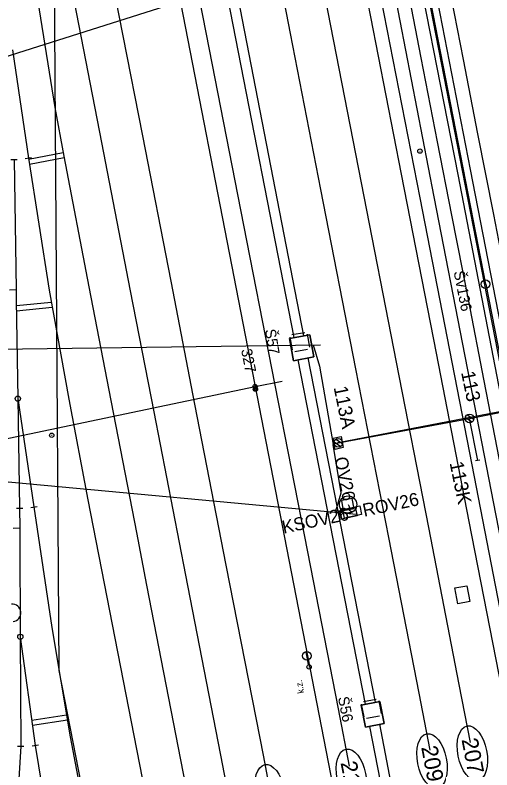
# Model space of a CAD drawing. Extents: x -545846 to -545044, y -1122650 to -1119108.
# Drawn here: x -545610 to -545555, y -1120099.3 to -1120012.2 of the extents above; entities that cross this region are included whole.
import ezdxf

# ---------------------------------------------------------------- set-up
doc = ezdxf.new("R2010")
doc.units = 0
for name, color, linetype in [('osvětlené plochy-hodnota-obrys', 7, 'Continuous'), ('Vrstva 1', 7, 'Continuous'), ('Vrstva 1 - Koleje', 7, 'Continuous'), ('Vrstva 11', 7, 'Continuous'), ('Vrstva 11 - Trakce', 7, 'Continuous'), ('Vrstva 12', 7, 'Continuous'), ('Vrstva 12 - Trakce zaklady', 7, 'Continuous'), ('Vrstva 2', 7, 'Continuous'), ('Vrstva 25', 7, 'Continuous'), ('Vrstva 26', 7, 'Continuous'), ('Vrstva 28', 7, 'Continuous'), ('Vrstva 34', 7, 'Continuous'), ('Vrstva 35', 7, 'Continuous'), ('Vrstva 36', 7, 'Continuous'), ('Vrstva 4 - Teren - stezky - prechody - plochy', 7, 'Continuous'), ('Vrstva 43', 7, 'Continuous'), ('Vrstva 44', 7, 'Continuous'), ('Vrstva 47', 7, 'Continuous'), ('Vrstva 50', 7, 'Continuous'), ('Vrstva 63', 7, 'Continuous'), ('Vrstva 7', 7, 'Continuous')]:
    doc.layers.add(name, color=color, linetype=linetype)

msp = doc.modelspace()

# ---------------------------------------------------------------- linework, layer by layer
at = {"layer": 'osvětlené plochy-hodnota-obrys'}
for points in [[(-545611.105, -1119760.367), (-545492.389, -1120368.615), (-545475.582, -1120447.487)], [(-545604.967, -1120087.817), (-545606.006, -1119933.661)], [(-545605.8, -1119934.355), (-545489.142, -1120534.587)], [(-545615.945, -1120078.719), (-545593.529, -1120193.57), (-545569.431, -1120317.038), (-545566.209, -1120328.419), (-545557.447, -1120326.084), (-545560.545, -1120315.165), (-545604.967, -1120087.817)]]:
    msp.add_lwpolyline(points, dxfattribs=at)
at = {"layer": 'Vrstva 1'}
for p, q in [((-545610.354, -1120016.231), (-545608.497, -1120028.715)), ((-545610.162, -1120028.86), (-545609.926, -1120043.87)), ((-545609.723, -1120056.452), (-545607.858, -1120068.952)), ((-545609.519, -1120069.093), (-545609.478, -1120071.372)), ((-545609.435, -1120083.923), (-545607.718, -1120096.482))]:
    msp.add_line(p, q, dxfattribs=at)
for points in [[(-545612.685, -1119787.025), (-545611.094, -1119796.357), (-545607.898, -1119813.098), (-545602.376, -1119841.635), (-545599.033, -1119858.8), (-545594.075, -1119884.173), (-545590.564, -1119902.118), (-545586.815, -1119921.29), (-545582.879, -1119941.487), (-545579.286, -1119959.902), (-545575.686, -1119978.306), (-545572.135, -1119996.454), (-545569.055, -1120012.422), (-545565.503, -1120030.558), (-545561.469, -1120051.222), (-545557.681, -1120070.616), (-545552.89, -1120095.213)], [(-545608.646, -1119843.243), (-545607.968, -1119853.947), (-545604.823, -1119878.324), (-545603.305, -1119886.455), (-545599.914, -1119903.772), (-545596.132, -1119922.876), (-545592.141, -1119943.299), (-545588.525, -1119961.8), (-545584.866, -1119980.43), (-545581.323, -1119998.614), (-545578.302, -1120014.333), (-545574.804, -1120032.326), (-545570.752, -1120053.023), (-545566.972, -1120072.457), (-545563.466, -1120090.434), (-545562.18, -1120097.022)], [(-545606.987, -1119843.017), (-545604.21, -1119857.163), (-545602.511, -1119865.793), (-545598.648, -1119885.403), (-545595.218, -1119902.774), (-545591.451, -1119922.067), (-545587.506, -1119942.313), (-545583.903, -1119960.798), (-545580.295, -1119979.3), (-545576.721, -1119997.623), (-545573.654, -1120013.453), (-545570.125, -1120031.548), (-545566.069, -1120052.247), (-545562.354, -1120071.317), (-545558.831, -1120089.437), (-545557.527, -1120096.116)], [(-545606.489, -1119916.134), (-545602.042, -1119941.851), (-545598.462, -1119960.658), (-545594.656, -1119980.253), (-545590.686, -1120000.64), (-545587.651, -1120016.178), (-545584.022, -1120034.678), (-545580.073, -1120054.893), (-545576.301, -1120074.138), (-545572.767, -1120092.238), (-545571.478, -1120098.833)], [(-545609.773, -1119946.287), (-545607.246, -1119962.958), (-545605.546, -1119973.067), (-545602.299, -1119990.174), (-545599.861, -1120003.011), (-545595.351, -1120026.149), (-545592.088, -1120042.905), (-545589.326, -1120057.082), (-545585.714, -1120075.648), (-545581.397, -1120097.788), (-545580.84, -1120100.656)], [(-545609.349, -1119973.764), (-545606.766, -1119991.45), (-545605.151, -1120000.686), (-545604.54, -1120003.913), (-545600.08, -1120026.893), (-545596.768, -1120044.006), (-545594.04, -1120057.971), (-545590.384, -1120076.827), (-545586.111, -1120098.754), (-545585.561, -1120101.575)], [(-545608.92, -1120001.258), (-545605.448, -1120022.876), (-545604.409, -1120028.503), (-545601.548, -1120043.573), (-545599.24, -1120055.486), (-545596.038, -1120071.891), (-545594.862, -1120077.975), (-545590.095, -1120102.458)], [(-545608.497, -1120028.715), (-545606.117, -1120043.922), (-545603.854, -1120056.524), (-545601.635, -1120068.115), (-545594.773, -1120103.368)], [(-545609.926, -1120043.87), (-545609.898, -1120045.09), (-545609.723, -1120056.452), (-545609.519, -1120069.093)], [(-545607.858, -1120068.952), (-545605.812, -1120082.859), (-545603.678, -1120095.483), (-545601.914, -1120104.759)], [(-545609.478, -1120071.372), (-545609.476, -1120072.56), (-545609.435, -1120083.923), (-545609.392, -1120096.553)], [(-545609.392, -1120096.553), (-545610.178, -1120109.783), (-545610.184, -1120109.845)], [(-545607.718, -1120096.482), (-545606.226, -1120105.598)]]:
    msp.add_lwpolyline(points, dxfattribs=at)
for centre in [(-545557.281, -1120097.365), (-545561.936, -1120098.253), (-545571.24, -1120100.029), (-545580.617, -1120101.818)]:
    msp.add_ellipse(centre, major_axis=(0.614, -3.151), ratio=0.521067, dxfattribs=at)
at = {"layer": 'Vrstva 1 - Koleje'}
for points in [[(-545565.242, -1120006.761), (-545563.215, -1120017.132), (-545561.328, -1120026.813), (-545559.685, -1120035.275), (-545557.783, -1120045.016), (-545555.954, -1120054.415), (-545553.446, -1120067.277), (-545551.651, -1120076.487), (-545549.618, -1120086.89), (-545547.731, -1120096.57), (-545545.899, -1120105.967), (-545543.904, -1120116.213), (-545541.838, -1120126.795), (-545539.892, -1120136.779), (-545537.95, -1120146.749), (-545536.037, -1120156.578), (-545534.37, -1120165.141), (-545532.743, -1120173.486), (-545531.198, -1120181.414)], [(-545560.08, -1120008.438), (-545558.344, -1120017.351), (-545556.681, -1120025.905), (-545554.861, -1120035.223), (-545552.908, -1120045.228), (-545550.866, -1120055.726), (-545548.758, -1120066.525), (-545547.531, -1120072.803), (-545545.346, -1120084.006), (-545543.28, -1120094.6), (-545541.202, -1120105.269), (-545539.263, -1120115.208), (-545537.306, -1120125.3), (-545535.418, -1120134.997), (-545533.428, -1120145.199), (-545531.528, -1120154.933), (-545529.681, -1120164.388), (-545527.503, -1120175.582), (-545525.637, -1120185.143)]]:
    msp.add_lwpolyline(points, dxfattribs=at)
at = {"layer": 'Vrstva 11'}
for p, q in [((-545582.113, -1120055.115), (-545582.497, -1120054.856)), ((-545582.221, -1120055.269), (-545582.599, -1120055.013)), ((-545582.183, -1120055.574), (-545582.562, -1120055.319)), ((-545582.076, -1120055.42), (-545582.46, -1120055.162))]:
    msp.add_line(p, q, dxfattribs=at)
msp.add_lwpolyline([(-545613.916, -1120061.683), (-545582.355, -1120055.06), (-545579.208, -1120054.45)], dxfattribs=at)
for centre in [(-545582.355, -1120055.06), (-545582.318, -1120055.365)]:
    msp.add_circle(centre, 0.25, dxfattribs=at)
at = {"layer": 'Vrstva 11 - Trakce'}
for p, q in [((-545557.873, -1120058.318), (-545557.11, -1120058.822)), ((-545558.085, -1120058.627), (-545557.312, -1120059.137)), ((-545556.669, -1120063.591), (-545557.6, -1120058.733)), ((-545573.234, -1120061.446), (-545572.461, -1120061.956)), ((-545573.022, -1120061.137), (-545572.259, -1120061.641)), ((-545556.421, -1120063.54), (-545556.911, -1120063.641))]:
    msp.add_line(p, q, dxfattribs=at)
msp.add_lwpolyline([(-545572.749, -1120061.552), (-545557.6, -1120058.733), (-545538.933, -1120055.016), (-545520.16, -1120051.364), (-545495.652, -1120046.54)], dxfattribs=at)
for centre in [(-545557.6, -1120058.733), (-545572.749, -1120061.552)]:
    msp.add_circle(centre, 0.5, dxfattribs=at)
at = {"layer": 'Vrstva 12'}
for points in [[(-545570.911, -1120069.151), (-545571.143, -1120067.954), (-545572.349, -1120068.192)], [(-545570.911, -1120069.151), (-545572.141, -1120069.412), (-545572.349, -1120068.192)]]:
    msp.add_lwpolyline(points, dxfattribs=at)
at = {"layer": 'Vrstva 12 - Trakce zaklady'}
for points in [[(-545573.36, -1120061.018), (-545572.421, -1120060.82), (-545572.176, -1120062.1), (-545573.097, -1120062.302), (-545573.36, -1120061.018)], [(-545570.911, -1120069.151), (-545571.143, -1120067.954), (-545572.349, -1120068.192)], [(-545570.911, -1120069.151), (-545572.141, -1120069.412), (-545572.349, -1120068.192)]]:
    msp.add_lwpolyline(points, dxfattribs=at)
at = {"layer": 'Vrstva 2'}
for p, q in [((-545610.354, -1120016.231), (-545608.497, -1120028.715)), ((-545608.127, -1120028.657), (-545608.867, -1120028.773)), ((-545610.537, -1120028.866), (-545609.787, -1120028.854)), ((-545610.697, -1120043.884), (-545609.926, -1120043.87)), ((-545609.723, -1120056.452), (-545607.858, -1120068.952)), ((-545609.894, -1120069.1), (-545609.144, -1120069.086)), ((-545608.229, -1120069.007), (-545607.487, -1120068.897)), ((-545610.249, -1120071.388), (-545609.478, -1120071.372)), ((-545609.435, -1120083.923), (-545607.718, -1120096.482)), ((-545609.767, -1120096.545), (-545609.017, -1120096.561)), ((-545607.348, -1120096.421), (-545608.088, -1120096.543))]:
    msp.add_line(p, q, dxfattribs=at)
for points in [[(-545609.926, -1120043.87), (-545609.898, -1120045.09), (-545609.723, -1120056.452), (-545609.519, -1120069.093)], [(-545609.478, -1120071.372), (-545609.476, -1120072.56), (-545609.435, -1120083.923), (-545609.392, -1120096.553)]]:
    msp.add_lwpolyline(points, dxfattribs=at)
for centre in [(-545609.723, -1120056.452), (-545609.435, -1120083.923)]:
    msp.add_circle(centre, 0.3, dxfattribs=at)
at = {"layer": 'Vrstva 25'}
for points in [[(-545572.773, -1120061.531), (-545538.933, -1120055.016)], [(-545570.276, -1120068.833), (-545570.068, -1120069.812), (-545572.024, -1120070.227), (-545572.232, -1120069.248), (-545570.276, -1120068.833)], [(-545572.534, -1120070.377), (-545572.742, -1120069.398), (-545570.786, -1120068.983), (-545570.578, -1120069.962), (-545572.534, -1120070.377)]]:
    msp.add_lwpolyline(points, dxfattribs=at)
msp.add_circle((-545571.63, -1120068.672), 1, dxfattribs=at)
msp.add_arc((-545610.363, -1120081.165), 1, 275.6954, 95.6954, dxfattribs=at)
at = {"layer": 'Vrstva 26'}
for points in [[(-545575.64, -1120050.263), (-545574.916, -1120052.707), (-545573.359, -1120061.728), (-545573.246, -1120061.659), (-545572.869, -1120061.594), (-545572.773, -1120061.531)], [(-545571.63, -1120068.672), (-545571.51, -1120068.91), (-545571.48, -1120069.32), (-545571.15, -1120069.53), (-545571.66, -1120069.68), (-545573.02, -1120069.41), (-545572.439, -1120067.308), (-545573.359, -1120061.728)], [(-545571.66, -1120069.68), (-545571.66, -1120069.68)], [(-545571.15, -1120069.53), (-545571.15, -1120069.53)]]:
    msp.add_lwpolyline(points, dxfattribs=at)
at = {"layer": 'Vrstva 28'}
msp.add_line((-545576.109, -1120087.424), (-545576.119, -1120087.374), dxfattribs=at)
msp.add_circle((-545576.114, -1120087.399), 0.25, dxfattribs=at)
at = {"layer": 'Vrstva 34'}
for p, q in [((-545578.102, -1120049.072), (-545576.624, -1120048.819)), ((-545578.053, -1120050.839), (-545578.306, -1120049.361)), ((-545576.335, -1120049.023), (-545576.082, -1120050.501)), ((-545576.286, -1120050.79), (-545577.764, -1120051.043)), ((-545569.857, -1120091.4), (-545568.384, -1120091.121)), ((-545568.091, -1120091.32), (-545567.812, -1120092.793)), ((-545569.777, -1120093.166), (-545570.056, -1120091.693)), ((-545568.011, -1120093.086), (-545569.484, -1120093.365))]:
    msp.add_line(p, q, dxfattribs=at)
at = {"layer": 'Vrstva 35'}
for p, q in [((-545576.708, -1120049.201), (-545584.415, -1120009.605)), ((-545577.834, -1120049.404), (-545585.571, -1120009.855)), ((-545569.623, -1120091.707), (-545577.372, -1120051.977)), ((-545568.453, -1120091.472), (-545576.243, -1120051.763))]:
    msp.add_line(p, q, dxfattribs=at)
for points in [[(-545560.376, -1120133.685), (-545567.955, -1120094.019)], [(-545561.385, -1120133.863), (-545569.121, -1120094.259)]]:
    msp.add_lwpolyline(points, dxfattribs=at)
at = {"layer": 'Vrstva 36'}
for points in [[(-545578.377, -1120049.501), (-545576.021, -1120049.077), (-545575.566, -1120051.633), (-545577.923, -1120052.079)], [(-545570.124, -1120091.806), (-545567.974, -1120091.373), (-545567.474, -1120093.919), (-545569.619, -1120094.359)]]:
    msp.add_lwpolyline(points, close=True, dxfattribs=at)
for points in [[(-545575.566, -1120051.633), (-545576.021, -1120049.077), (-545578.377, -1120049.501), (-545578.377, -1120049.501)], [(-545578.377, -1120049.501), (-545577.923, -1120052.079), (-545577.923, -1120052.079)], [(-545576.021, -1120049.077), (-545576.021, -1120049.077)], [(-545577.923, -1120052.079), (-545575.566, -1120051.633), (-545575.566, -1120051.633)], [(-545567.974, -1120091.373), (-545570.124, -1120091.806)], [(-545567.474, -1120093.919), (-545567.974, -1120091.373), (-545567.974, -1120091.373)], [(-545570.124, -1120091.806), (-545570.124, -1120091.806), (-545569.619, -1120094.359), (-545569.619, -1120094.359)], [(-545569.619, -1120094.359), (-545567.474, -1120093.919), (-545567.474, -1120093.919)]]:
    msp.add_lwpolyline(points, dxfattribs=at)
at = {"layer": 'Vrstva 4 - Teren - stezky - prechody - plochy'}
for points in [[(-545488.754, -1120379.549), (-545491.925, -1120363.788), (-545496.278, -1120342.782), (-545500.506, -1120321.731), (-545508.599, -1120280.828), (-545518.82, -1120228.621), (-545531.029, -1120165.923), (-545540.626, -1120116.248), (-545552.245, -1120057.042), (-545557.488, -1120030.03), (-545563.439, -1119999.512), (-545572.128, -1119954.79), (-545581.61, -1119906.246), (-545591.458, -1119855.639), (-545600.962, -1119806.943), (-545610.434, -1119758.233), (-545616.648, -1119726.461), (-545621.696, -1119701.088), (-545622.533, -1119696.196), (-545623.462, -1119696.331)], [(-545490.916, -1120379.972), (-545493.99, -1120364.147), (-545502.163, -1120322.09), (-545510.164, -1120281.035), (-545520.235, -1120229.023), (-545532.517, -1120166.017), (-545542.296, -1120116.028), (-545553.809, -1120057.082), (-545558.932, -1120030.597), (-545564.969, -1119999.794), (-545573.753, -1119955.036), (-545583.127, -1119906.578), (-545593.017, -1119855.856), (-545602.553, -1119806.891), (-545612.123, -1119758.671), (-545618.333, -1119726.047), (-545620.676, -1119713.873), (-545622.612, -1119701.558), (-545623.462, -1119696.331)], [(-545495.535, -1120380.876), (-545498.596, -1120365.093), (-545507.092, -1120321.572), (-545515.017, -1120281.173), (-545524.994, -1120229.535), (-545536.771, -1120169.47), (-545546.676, -1120118.787), (-545557.312, -1120064.079), (-545563.312, -1120033.308), (-545569.884, -1119999.645), (-545578.452, -1119955.82), (-545587.921, -1119907.338), (-545597.812, -1119856.591), (-545607.33, -1119807.681), (-545610.119, -1119793.19), (-545611.535, -1119784.447), (-545612.6, -1119777.287), (-545613.018, -1119774.47), (-545612.047, -1119774.376)], [(-545493.924, -1120380.561), (-545496.951, -1120365.161), (-545505.376, -1120321.611), (-545513.278, -1120281.443), (-545523.478, -1120229.493), (-545535.102, -1120169.56), (-545545.054, -1120118.579), (-545554.55, -1120069.937), (-545561.701, -1120033.181), (-545568.213, -1119999.317), (-545576.806, -1119955.508), (-545586.262, -1119907.136), (-545605.677, -1119807.326), (-545612.047, -1119774.376)]]:
    msp.add_lwpolyline(points, dxfattribs=at)
at = {"layer": 'Vrstva 43'}
msp.add_line((-545576.188, -1120087.114), (-545576.47, -1120085.643), dxfattribs=at)
for centre, radius in [((-545555.77, -1120043.249), 0.5), ((-545576.376, -1120086.132), 0.498)]:
    msp.add_circle(centre, radius, dxfattribs=at)
at = {"layer": 'Vrstva 44'}
for points in [[(-545555.749, -1120043.26), (-545564.433, -1119998.625), (-545572.978, -1119955.082), (-545572.96, -1119954.967)], [(-545555.749, -1120043.26), (-545546.419, -1120090.806), (-545536.389, -1120141.112), (-545536.421, -1120141.276)]]:
    msp.add_lwpolyline(points, dxfattribs=at)
at = {"layer": 'Vrstva 47'}
msp.add_lwpolyline([(-545558.979, -1120080.124), (-545559.324, -1120078.264), (-545557.939, -1120078.039), (-545557.578, -1120079.871)], close=True, dxfattribs=at)
at = {"layer": 'Vrstva 50'}
for p, q in [((-545563.352, -1120027.906), (-545563.302, -1120027.906)), ((-545605.83, -1120060.681), (-545605.78, -1120060.681))]:
    msp.add_line(p, q, dxfattribs=at)
for centre in [(-545563.327, -1120027.906), (-545605.805, -1120060.681)]:
    msp.add_circle(centre, 0.25, dxfattribs=at)
at = {"layer": 'Vrstva 63'}
for p, q in [((-545583.044, -1120008.072), (-545662.585, -1120033.421)), ((-545574.802, -1120050.301), (-545659.068, -1120051.395)), ((-545570.64, -1120069.812), (-545649.082, -1120062.538))]:
    msp.add_line(p, q, dxfattribs=at)
at = {"layer": 'Vrstva 7'}
for p, q in [((-545608.481, -1120028.822), (-545604.491, -1120028.057)), ((-545608.387, -1120029.415), (-545604.382, -1120028.647)), ((-545609.888, -1120045.715), (-545605.865, -1120045.326)), ((-545609.879, -1120046.317), (-545605.759, -1120045.918)), ((-545604.103, -1120092.969), (-545608.114, -1120093.582)), ((-545604.003, -1120093.56), (-545608.033, -1120094.176))]:
    msp.add_line(p, q, dxfattribs=at)

# ---------------------------------------------------------------- texts
at = {"layer": 'Vrstva 11'}
msp.add_text('327', height=1.25, rotation=281.07283, dxfattribs=at).set_placement((-545583.972, -1120050.821))
at = {"layer": 'Vrstva 11 - Trakce'}
for s, p in [('113', (-545558.593, -1120053.423)), ('113A', (-545573.3, -1120055.149)), ('113K', (-545559.919, -1120063.861))]:
    msp.add_text(s, height=1.6, rotation=281.5757, dxfattribs=at).set_placement(p)
at = {"layer": 'Vrstva 2'}
for s, p in [('207', (-545558.541, -1120095.78)), ('209', (-545563.197, -1120096.668)), ('211', (-545572.5, -1120098.444))]:
    msp.add_text(s, height=1.875, rotation=280.91172, dxfattribs=at).set_placement(p)
at = {"layer": 'Vrstva 25'}
for s, rotation, p in [('OV26', 280.96895, (-545573.191, -1120063.314)), ('ROV26', 11.98018, (-545569.767, -1120070.088)), ('KSOV26', 11.98018, (-545579.063, -1120072.036))]:
    msp.add_text(s, height=1.5, rotation=rotation, dxfattribs=at).set_placement(p)
at = {"layer": 'Vrstva 28'}
msp.add_text('k.z.', height=0.75, rotation=101.04938, dxfattribs=at).set_placement((-545576.677, -1120090.387))
at = {"layer": 'Vrstva 34'}
for s, rotation, p in [('Š57', 279.7291, (-545581.233, -1120048.525)), ('Š56', 280.75298, (-545572.79, -1120090.929))]:
    msp.add_text(s, height=1.25, rotation=rotation, dxfattribs=at).set_placement(p)
at = {"layer": 'Vrstva 43'}
msp.add_text('Šv136', height=1.25, rotation=280.99979, dxfattribs=at).set_placement((-545559.451, -1120041.818))

doc.saveas('drawing.dxf')
